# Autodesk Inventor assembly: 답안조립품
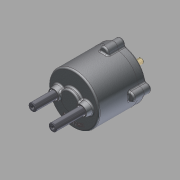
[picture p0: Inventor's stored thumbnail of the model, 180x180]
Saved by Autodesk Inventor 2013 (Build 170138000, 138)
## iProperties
Created: 2015-02
Part Number: 답안조립품
Document SubType Name: Assembly
Designer: Administrator
Mass: 1967.31 g
Surface Area: 1692.74 cm^2
Volume: 412.889 cm^3
Density: 4.76474 g/cm^3
Author: Administrator
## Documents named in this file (13)
- C:\Users\Administrator\Desktop\350208V1015\답안조립품.iam
- C:\Users\Administrator\Desktop\350208V1015\몸체.ipt
- C:\Users\Administrator\Desktop\350208V1015\메인 축.ipt
- C:\Users\Administrator\Desktop\350208V1015\베어링 NA 4900.ipt
- C:\Users\Administrator\Desktop\350208V1015\멈춤링 10 x 1.ipt
- C:\Users\Administrator\Desktop\350208V1015\판캠.ipt
- C:\Users\Administrator\Desktop\350208V1015\멈춤링 22 x 1.2.ipt
- C:\Users\Administrator\Desktop\350208V1015\커버.ipt
- C:\Users\Administrator\Desktop\350208V1015\오일실.ipt
- C:\Users\Administrator\Desktop\350208V1015\M5x0.5x20.ipt
- C:\Users\Administrator\Desktop\350208V1015\슬라이드 축.ipt
- C:\Users\Administrator\Desktop\350208V1015\가변스프링1.ipt
- C:\Users\Administrator\Desktop\350208V1015\가변스프링2.ipt
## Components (6 placed, 3 different names)
1. M5x0.5x20:1
2. M5x0.5x20:2
3. M5x0.5x20:3
4. M5x0.5x20:4
5. 가변스프링1:1
6. 가변스프링2:1
